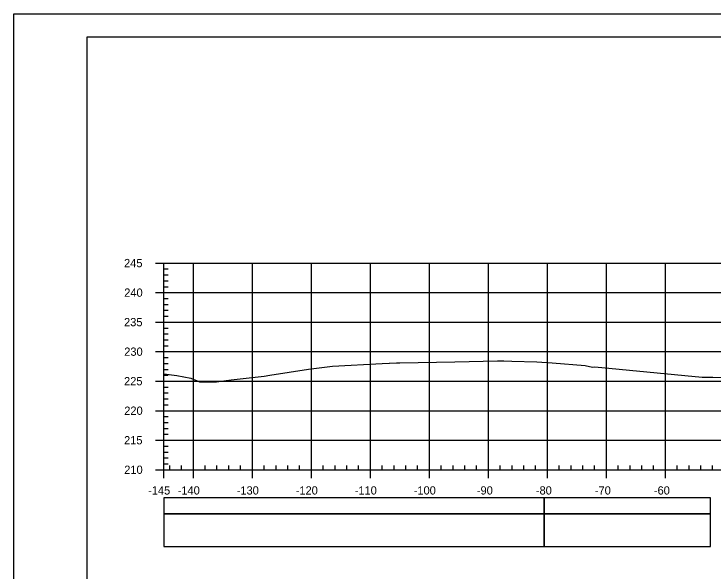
# Model space of a CAD drawing. Extents: x 1386544 to 1388153, y 379785 to 390999.
# Drawn here: x 1387761.6 to 1387880, y 380637.8 to 380732.1 of the extents above; entities that cross this region are included whole.
import ezdxf

# ---------------------------------------------------------------- set-up
doc = ezdxf.new("R2010")
doc.units = 0
for name, color, linetype in [('R_Axis', 7, 'Continuous'), ('R_Axis Annot', 7, 'Continuous'), ('R_Border', 7, 'Continuous'), ('R_Exist Surface', 7, 'Continuous'), ('R_Grid', 7, 'Continuous'), ('R_No Plot', 7, 'Continuous'), ('R_Striping', 7, 'Continuous')]:
    doc.layers.add(name, color=color, linetype=linetype)

msp = doc.modelspace()

# ---------------------------------------------------------------- linework, layer by layer
at = {"layer": 'R_Axis'}
for p, q in [((1387785.57, 380689.95), (1387786.97, 380689.95)), ((1387786.97, 380654.95), (1387786.97, 380689.95)), ((1387786.97, 380688.95), (1387787.67, 380688.95)), ((1387786.97, 380687.95), (1387787.67, 380687.95)), ((1387786.97, 380686.95), (1387787.67, 380686.95)), ((1387786.97, 380685.95), (1387787.67, 380685.95)), ((1387785.57, 380684.95), (1387786.97, 380684.95)), ((1387786.97, 380683.95), (1387787.67, 380683.95)), ((1387786.97, 380682.95), (1387787.67, 380682.95)), ((1387786.97, 380681.95), (1387787.67, 380681.95)), ((1387786.97, 380680.95), (1387787.67, 380680.95)), ((1387785.57, 380679.95), (1387786.97, 380679.95)), ((1387786.97, 380678.95), (1387787.67, 380678.95)), ((1387786.97, 380677.95), (1387787.67, 380677.95)), ((1387786.97, 380676.95), (1387787.67, 380676.95)), ((1387786.97, 380675.95), (1387787.67, 380675.95)), ((1387785.57, 380674.95), (1387786.97, 380674.95)), ((1387786.97, 380673.95), (1387787.67, 380673.95)), ((1387786.97, 380672.95), (1387787.67, 380672.95)), ((1387786.97, 380671.95), (1387787.67, 380671.95)), ((1387785.57, 380669.95), (1387786.97, 380669.95)), ((1387786.97, 380670.95), (1387787.67, 380670.95)), ((1387786.97, 380668.95), (1387787.67, 380668.95)), ((1387786.97, 380667.95), (1387787.67, 380667.95)), ((1387786.97, 380666.95), (1387787.67, 380666.95)), ((1387786.97, 380665.95), (1387787.67, 380665.95)), ((1387785.57, 380664.95), (1387786.97, 380664.95)), ((1387786.97, 380663.95), (1387787.67, 380663.95)), ((1387786.97, 380662.95), (1387787.67, 380662.95)), ((1387786.97, 380661.95), (1387787.67, 380661.95)), ((1387786.97, 380660.95), (1387787.67, 380660.95)), ((1387785.57, 380659.95), (1387786.97, 380659.95)), ((1387786.97, 380658.95), (1387787.67, 380658.95)), ((1387786.97, 380657.95), (1387787.67, 380657.95)), ((1387786.97, 380656.95), (1387787.67, 380656.95)), ((1387786.97, 380655.95), (1387787.67, 380655.95)), ((1387786.97, 380654.95), (1387786.97, 380655.65)), ((1387787.97, 380654.95), (1387787.97, 380655.65)), ((1387789.97, 380654.95), (1387789.97, 380655.65)), ((1387793.97, 380654.95), (1387793.97, 380655.65)), ((1387795.97, 380654.95), (1387795.97, 380655.65)), ((1387797.97, 380654.95), (1387797.97, 380655.65)), ((1387799.97, 380654.95), (1387799.97, 380655.65)), ((1387803.97, 380654.95), (1387803.97, 380655.65)), ((1387805.97, 380654.95), (1387805.97, 380655.65)), ((1387807.97, 380654.95), (1387807.97, 380655.65)), ((1387809.97, 380654.95), (1387809.97, 380655.65)), ((1387813.97, 380654.95), (1387813.97, 380655.65)), ((1387815.97, 380654.95), (1387815.97, 380655.65)), ((1387817.97, 380654.95), (1387817.97, 380655.65)), ((1387819.97, 380654.95), (1387819.97, 380655.65)), ((1387823.97, 380654.95), (1387823.97, 380655.65)), ((1387825.97, 380654.95), (1387825.97, 380655.65)), ((1387827.97, 380654.95), (1387827.97, 380655.65)), ((1387829.97, 380654.95), (1387829.97, 380655.65)), ((1387833.97, 380654.95), (1387833.97, 380655.65)), ((1387835.97, 380654.95), (1387835.97, 380655.65)), ((1387837.97, 380654.95), (1387837.97, 380655.65)), ((1387839.97, 380654.95), (1387839.97, 380655.65)), ((1387843.97, 380654.95), (1387843.97, 380655.65)), ((1387845.97, 380654.95), (1387845.97, 380655.65)), ((1387847.97, 380654.95), (1387847.97, 380655.65)), ((1387849.97, 380654.95), (1387849.97, 380655.65)), ((1387853.97, 380654.95), (1387853.97, 380655.65)), ((1387855.97, 380654.95), (1387855.97, 380655.65)), ((1387857.97, 380654.95), (1387857.97, 380655.65)), ((1387859.97, 380654.95), (1387859.97, 380655.65)), ((1387863.97, 380654.95), (1387863.97, 380655.65)), ((1387865.97, 380654.95), (1387865.97, 380655.65)), ((1387867.97, 380654.95), (1387867.97, 380655.65)), ((1387869.97, 380654.95), (1387869.97, 380655.65)), ((1387873.97, 380654.95), (1387873.97, 380655.65)), ((1387875.97, 380654.95), (1387875.97, 380655.65)), ((1387877.97, 380654.95), (1387877.97, 380655.65)), ((1387879.97, 380654.95), (1387879.97, 380655.65)), ((1387785.57, 380654.95), (1387786.97, 380654.95)), ((1387786.97, 380654.95), (1388076.97, 380654.95)), ((1387786.97, 380653.55), (1387786.97, 380654.95)), ((1387791.97, 380653.55), (1387791.97, 380654.95)), ((1387801.97, 380653.55), (1387801.97, 380654.95)), ((1387811.97, 380653.55), (1387811.97, 380654.95)), ((1387821.97, 380653.55), (1387821.97, 380654.95)), ((1387831.97, 380653.55), (1387831.97, 380654.95)), ((1387841.97, 380653.55), (1387841.97, 380654.95)), ((1387851.97, 380653.55), (1387851.97, 380654.95)), ((1387861.97, 380653.55), (1387861.97, 380654.95)), ((1387871.97, 380653.55), (1387871.97, 380654.95))]:
    msp.add_line(p, q, dxfattribs=at)
at = {"layer": 'R_Axis Annot'}
for points in [[(1387786.97, 380647.5), (1387851.41, 380647.5), (1387851.41, 380650.21), (1387786.97, 380650.21)], [(1387786.97, 380641.98), (1387851.41, 380641.98), (1387851.41, 380647.5), (1387786.97, 380647.5)]]:
    msp.add_lwpolyline(points, close=True, dxfattribs=at)
at = {"layer": 'R_Border'}
for p, q in [((1387773.97, 380728.24), (1388090.15, 380728.24)), ((1387773.97, 380522.78), (1387773.97, 380728.24))]:
    msp.add_line(p, q, dxfattribs=at)
at = {"layer": 'R_Exist Surface'}
msp.add_lwpolyline([(1387786.97, 380671.22), (1387789.14, 380670.93), (1387791.52, 380670.45), (1387793.03, 380669.86), (1387794.98, 380669.84), (1387795.9, 380669.86), (1387798.35, 380670.17), (1387803.96, 380670.81), (1387804.94, 380670.95), (1387811.46, 380671.97), (1387815.54, 380672.51), (1387823.94, 380672.93), (1387825.14, 380672.99), (1387825.22, 380673), (1387826.37, 380673.05), (1387826.62, 380673.05), (1387826.93, 380673.06), (1387836.26, 380673.24), (1387843.51, 380673.39), (1387843.77, 380673.38), (1387844.57, 380673.38), (1387845.96, 380673.33), (1387850.19, 380673.23), (1387852.76, 380673.06), (1387858.35, 380672.6), (1387859.6, 380672.32), (1387859.92, 380672.37), (1387861.17, 380672.27), (1387878.2, 380670.63), (1387878.88, 380670.63), (1387880, 380670.62), (1387902.39, 380670.49)], dxfattribs=at)
at = {"layer": 'R_Grid'}
for p, q in [((1387786.97, 380689.95), (1388076.97, 380689.95)), ((1387786.97, 380654.95), (1387786.97, 380689.95)), ((1387791.97, 380654.95), (1387791.97, 380689.95)), ((1387801.97, 380654.95), (1387801.97, 380689.95)), ((1387811.97, 380654.95), (1387811.97, 380689.95)), ((1387821.97, 380654.95), (1387821.97, 380689.95)), ((1387831.97, 380654.95), (1387831.97, 380689.95)), ((1387841.97, 380654.95), (1387841.97, 380689.95)), ((1387851.97, 380654.95), (1387851.97, 380689.95)), ((1387861.97, 380654.95), (1387861.97, 380689.95)), ((1387871.97, 380654.95), (1387871.97, 380689.95)), ((1387786.97, 380684.95), (1388076.97, 380684.95)), ((1387786.97, 380679.95), (1388076.97, 380679.95)), ((1387786.97, 380674.95), (1388076.97, 380674.95)), ((1387786.97, 380669.95), (1388076.97, 380669.95)), ((1387786.97, 380664.95), (1388076.97, 380664.95)), ((1387786.97, 380659.95), (1388076.97, 380659.95)), ((1387786.97, 380654.95), (1388076.97, 380654.95))]:
    msp.add_line(p, q, dxfattribs=at)
at = {"layer": 'R_No Plot'}
msp.add_line((1387761.57, 380732.14), (1388094.9, 380732.14), dxfattribs=at)
for points in [[(1387761.56, 380732.14), (1388094.9, 380732.14), (1388094.9, 380518.8), (1387761.56, 380518.8)], [(1388007.89, 380728.24), (1388027.51, 380728.24), (1388027.51, 380718.36), (1388043.62, 380718.36), (1388066.82, 380718.36), (1388066.82, 380694.03), (1388090.15, 380694.03), (1388090.15, 380522.78), (1387773.97, 380522.78), (1387773.97, 380728.24)]]:
    msp.add_lwpolyline(points, close=True, dxfattribs=at)
at = {"layer": 'R_Striping'}
for points in [[(1387851.41, 380647.51), (1387879.6, 380647.51), (1387879.6, 380650.21), (1387851.41, 380650.21)], [(1387851.41, 380641.98), (1387879.6, 380641.98), (1387879.6, 380647.51), (1387851.41, 380647.51)]]:
    msp.add_lwpolyline(points, close=True, dxfattribs=at)

# ---------------------------------------------------------------- texts
at = {"layer": 'R_Axis Annot'}
for s, p in [('245', (1387780.22, 380689.25)), ('240', (1387780.25, 380684.25)), ('235', (1387780.22, 380679.25)), ('230', (1387780.25, 380674.25)), ('225', (1387780.22, 380669.25)), ('220', (1387780.25, 380664.25)), ('215', (1387780.22, 380659.25)), ('210', (1387780.25, 380654.25)), ('-145', (1387784.3, 380650.75)), ('-140', (1387789.31, 380650.75)), ('-130', (1387799.31, 380650.75)), ('-120', (1387809.31, 380650.75)), ('-110', (1387819.31, 380650.75)), ('-100', (1387829.31, 380650.75)), ('-90', (1387840.01, 380650.75)), ('-80', (1387850.01, 380650.75)), ('-70', (1387860.01, 380650.75)), ('-60', (1387870.01, 380650.75))]:
    msp.add_text(s, height=1.4, dxfattribs=at).set_placement(p)

doc.saveas('drawing.dxf')
